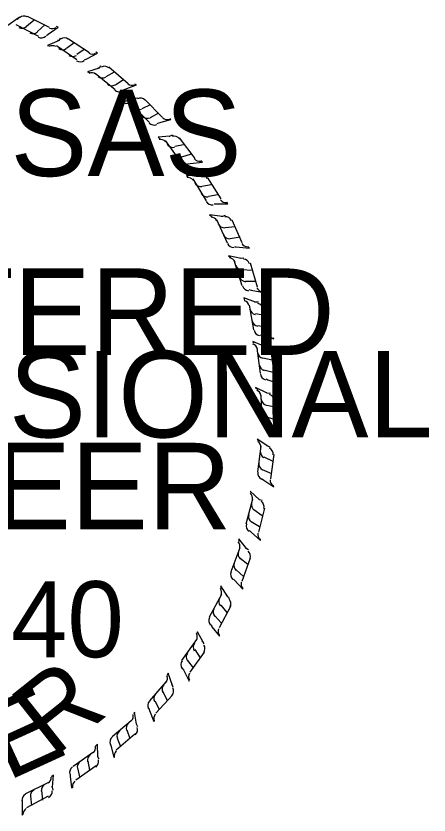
# Model space of a CAD drawing. Extents: x 1369528 to 1373075, y 373809 to 376031.
# Drawn here: x 1372751.6 to 1372841.2, y 373968.1 to 374141.3 of the extents above; entities that cross this region are included whole.
import ezdxf

# ---------------------------------------------------------------- set-up
doc = ezdxf.new("R2010")
doc.units = 0
doc.layers.add('R_Border Notes', color=7, linetype='Continuous')

msp = doc.modelspace()

# ---------------------------------------------------------------- linework, layer by layer
at = {"layer": 'R_Border Notes'}
for p, q in [((1372752.11, 374140.76), (1372749.83, 374139.2)), ((1372752.11, 374140.76), (1372751.87, 374140.52)), ((1372752.47, 374141), (1372752.11, 374140.76)), ((1372754.03, 374141.24), (1372758.83, 374138.84)), ((1372756.55, 374136.8), (1372751.63, 374139.32)), ((1372753.91, 374139.08), (1372755.59, 374140.4)), ((1372756.31, 374137.88), (1372757.87, 374139.32)), ((1372760.75, 374138.84), (1372760.39, 374138.96)), ((1372758.23, 374137.04), (1372758.59, 374137.28)), ((1372758.59, 374137.28), (1372760.75, 374138.84)), ((1372760.99, 374135.96), (1372758.47, 374134.88)), ((1372760.99, 374135.96), (1372760.63, 374135.96)), ((1372761.23, 374136.44), (1372760.99, 374135.96)), ((1372762.55, 374134.28), (1372764.23, 374135.48)), ((1372763.03, 374136.32), (1372767.59, 374133.32)), ((1372758.47, 374134.88), (1372758.83, 374134.76)), ((1372764.83, 374131.76), (1372760.39, 374134.76)), ((1372764.83, 374132.96), (1372766.39, 374134.04)), ((1372766.99, 374132), (1372769.27, 374133.2)), ((1372769.27, 374133.2), (1372768.91, 374133.44)), ((1372766.51, 374131.76), (1372766.99, 374132)), ((1372769.99, 374130.44), (1372769.63, 374129.96)), ((1372769.63, 374129.96), (1372767.11, 374129.12)), ((1372767.11, 374129.12), (1372767.59, 374129)), ((1372773.11, 374125.28), (1372768.79, 374128.76)), ((1372769.63, 374129.96), (1372769.39, 374129.96)), ((1372771.19, 374128.16), (1372772.99, 374129.12)), ((1372771.79, 374130.2), (1372775.99, 374126.6)), ((1372773.23, 374126.36), (1372775.03, 374127.56)), ((1372774.79, 374125.16), (1372775.27, 374125.4)), ((1372775.27, 374125.4), (1372777.79, 374126.36)), ((1372777.79, 374126.36), (1372777.43, 374126.48)), ((1372777.55, 374123.36), (1372775.03, 374122.64)), ((1372777.55, 374123.36), (1372777.31, 374123.12)), ((1372778.03, 374123.48), (1372777.55, 374123.36)), ((1372775.03, 374122.64), (1372775.39, 374122.28)), ((1372780.55, 374118.2), (1372776.59, 374122.16)), ((1372778.99, 374121.2), (1372780.79, 374122.04)), ((1372779.59, 374123.12), (1372783.43, 374119.28)), ((1372780.79, 374119.28), (1372782.59, 374120.24)), ((1372782.59, 374118.08), (1372785.23, 374118.8)), ((1372785.23, 374118.8), (1372784.99, 374119.04)), ((1372782.23, 374117.96), (1372782.59, 374118.08)), ((1372784.99, 374115.2), (1372782.47, 374114.96)), ((1372782.47, 374114.96), (1372782.83, 374114.6)), ((1372784.99, 374115.2), (1372784.87, 374115.08)), ((1372785.59, 374115.44), (1372784.99, 374115.2)), ((1372787.03, 374114.84), (1372790.39, 374110.4)), ((1372787.39, 374109.68), (1372784.03, 374114.24)), ((1372786.07, 374113.04), (1372787.99, 374113.4)), ((1372787.63, 374110.76), (1372789.67, 374111.36)), ((1372789.43, 374109.32), (1372792.07, 374109.56)), ((1372792.07, 374109.56), (1372791.71, 374109.92)), ((1372788.83, 374109.2), (1372789.43, 374109.32)), ((1372791.23, 374106.68), (1372788.59, 374106.68)), ((1372788.59, 374106.68), (1372788.83, 374106.32)), ((1372791.23, 374106.68), (1372790.99, 374106.8)), ((1372791.59, 374106.92), (1372791.23, 374106.68)), ((1372793.15, 374106.2), (1372796.03, 374101.64)), ((1372792.91, 374101.16), (1372790.03, 374105.96)), ((1372791.95, 374104.4), (1372793.99, 374104.76)), ((1372793.39, 374102.24), (1372795.43, 374102.6)), ((1372797.59, 374100.56), (1372797.35, 374100.92)), ((1372794.59, 374100.56), (1372794.95, 374100.56)), ((1372794.95, 374100.56), (1372797.59, 374100.56)), ((1372796.39, 374097.8), (1372793.63, 374098.16)), ((1372793.63, 374098.16), (1372794.11, 374097.8)), ((1372796.39, 374097.8), (1372796.15, 374097.8)), ((1372796.99, 374098.04), (1372796.39, 374097.8)), ((1372797.47, 374092.04), (1372795.19, 374097.08)), ((1372796.99, 374095.4), (1372799.15, 374095.64)), ((1372798.43, 374097.08), (1372800.59, 374092.16)), ((1372798.07, 374093), (1372800.23, 374093.36)), ((1372799.03, 374091.2), (1372799.39, 374091.2)), ((1372799.39, 374091.2), (1372802.27, 374090.96)), ((1372802.27, 374090.96), (1372801.91, 374091.32)), ((1372800.47, 374088.68), (1372797.71, 374089.28)), ((1372797.71, 374089.28), (1372798.19, 374088.92)), ((1372800.47, 374088.68), (1372800.23, 374088.8)), ((1372801.07, 374088.8), (1372800.47, 374088.68)), ((1372800.71, 374082.8), (1372799.03, 374088.08)), ((1372802.39, 374087.72), (1372803.95, 374082.56)), ((1372800.59, 374086.28), (1372802.87, 374086.16)), ((1372801.43, 374083.76), (1372803.59, 374083.76)), ((1372802.15, 374081.96), (1372802.63, 374081.84)), ((1372802.63, 374081.84), (1372805.39, 374081.36)), ((1372803.59, 374079.2), (1372801.07, 374080.16)), ((1372801.07, 374080.16), (1372801.19, 374079.56)), ((1372805.39, 374081.36), (1372805.03, 374081.6)), ((1372803.23, 374073.2), (1372802.27, 374078.6)), ((1372803.59, 374079.2), (1372803.35, 374079.2)), ((1372804.19, 374079.2), (1372803.59, 374079.2)), ((1372803.59, 374076.8), (1372805.63, 374076.44)), ((1372805.39, 374077.76), (1372806.35, 374072.6)), ((1372804.07, 374074.16), (1372806.11, 374073.8)), ((1372804.55, 374072.12), (1372805.03, 374072)), ((1372805.03, 374072), (1372807.55, 374071.28)), ((1372807.55, 374071.28), (1372807.43, 374071.52)), ((1372805.39, 374069.72), (1372802.99, 374070.68)), ((1372802.99, 374070.68), (1372803.11, 374070.32)), ((1372805.39, 374069.72), (1372805.15, 374069.72)), ((1372805.99, 374069.6), (1372805.39, 374069.72)), ((1372804.67, 374063.84), (1372803.95, 374069.24)), ((1372806.95, 374068.16), (1372807.67, 374062.76)), ((1372805.15, 374067.2), (1372807.19, 374066.72)), ((1372805.39, 374064.56), (1372807.43, 374064.08)), ((1372805.87, 374062.64), (1372806.23, 374062.4)), ((1372806.23, 374062.4), (1372808.75, 374061.56)), ((1372808.75, 374061.56), (1372808.63, 374061.8)), ((1372806.11, 374059.52), (1372803.59, 374060.72)), ((1372803.59, 374060.72), (1372804.07, 374060.36)), ((1372806.11, 374059.52), (1372805.99, 374059.64)), ((1372806.83, 374059.4), (1372806.11, 374059.52)), ((1372805.03, 374053.76), (1372804.79, 374059.16)), ((1372807.79, 374057.96), (1372808.15, 374052.56)), ((1372805.63, 374057), (1372807.91, 374056.52)), ((1372805.99, 374054.36), (1372808.03, 374053.76)), ((1372806.11, 374052.44), (1372806.59, 374052.2)), ((1372806.59, 374052.2), (1372808.99, 374051.12)), ((1372808.99, 374051.12), (1372808.99, 374051.36)), ((1372806.23, 374048), (1372803.95, 374049.56)), ((1372803.95, 374049.56), (1372804.19, 374049.08)), ((1372804.07, 374042.48), (1372804.79, 374048)), ((1372806.23, 374048), (1372805.99, 374048.12)), ((1372806.83, 374047.76), (1372806.23, 374048)), ((1372805.39, 374045.72), (1372807.31, 374044.76)), ((1372807.55, 374046.2), (1372806.83, 374040.92)), ((1372805.03, 374042.96), (1372807.07, 374042.12)), ((1372804.91, 374041.04), (1372805.39, 374040.68)), ((1372805.39, 374040.68), (1372807.55, 374039.24)), ((1372807.55, 374039.24), (1372807.43, 374039.6)), ((1372804.43, 374036.36), (1372802.39, 374038.28)), ((1372802.39, 374038.28), (1372802.63, 374037.8)), ((1372801.55, 374031.2), (1372802.99, 374036.6)), ((1372804.43, 374036.36), (1372804.19, 374036.6)), ((1372805.03, 374036.24), (1372804.43, 374036.36)), ((1372803.23, 374034.32), (1372805.03, 374033)), ((1372805.51, 374034.56), (1372804.19, 374029.4)), ((1372802.63, 374031.68), (1372804.43, 374030.6)), ((1372802.27, 374029.76), (1372802.63, 374029.4)), ((1372802.63, 374029.4), (1372804.67, 374027.6)), ((1372801.67, 374025.8), (1372799.99, 374027.96)), ((1372799.99, 374027.96), (1372799.99, 374027.36)), ((1372804.67, 374027.6), (1372804.67, 374027.96)), ((1372798.31, 374020.88), (1372800.23, 374026.04)), ((1372801.67, 374025.8), (1372801.43, 374025.92)), ((1372802.03, 374025.56), (1372801.67, 374025.8)), ((1372800.23, 374023.76), (1372801.91, 374022.44)), ((1372802.39, 374023.76), (1372800.59, 374018.72)), ((1372799.39, 374021.24), (1372800.95, 374019.8)), ((1372797.59, 374015.36), (1372796.03, 374017.76)), ((1372796.03, 374017.76), (1372796.03, 374017.16)), ((1372798.79, 374019.2), (1372799.03, 374018.96)), ((1372799.03, 374018.96), (1372800.83, 374017.04)), ((1372800.83, 374017.04), (1372800.83, 374017.28)), ((1372793.63, 374011.04), (1372796.27, 374015.96)), ((1372797.59, 374015.36), (1372797.47, 374015.6)), ((1372797.95, 374015), (1372797.59, 374015.36)), ((1372798.19, 374013.44), (1372795.67, 374008.64)), ((1372796.03, 374013.56), (1372797.35, 374012)), ((1372794.83, 374011.16), (1372796.15, 374009.72)), ((1372793.99, 374009.36), (1372794.11, 374008.88)), ((1372790.99, 374007.8), (1372790.87, 374007.44)), ((1372792.19, 374005.52), (1372790.99, 374007.8)), ((1372794.11, 374008.88), (1372795.79, 374006.84)), ((1372787.63, 374001.56), (1372790.87, 374006.12)), ((1372792.19, 374005.52), (1372791.95, 374005.76)), ((1372795.79, 374006.84), (1372795.79, 374007.2)), ((1372790.39, 374003.96), (1372791.59, 374002.16)), ((1372792.43, 374005.16), (1372792.19, 374005.52)), ((1372792.43, 374003.36), (1372789.31, 373999.04)), ((1372788.83, 374001.56), (1372790.03, 374000)), ((1372784.63, 373998.8), (1372784.39, 373998.32)), ((1372785.59, 373996.16), (1372784.63, 373998.8)), ((1372787.63, 374000), (1372787.99, 373999.52)), ((1372787.99, 373999.52), (1372789.19, 373997.12)), ((1372780.67, 373992.8), (1372784.27, 373997)), ((1372789.19, 373997.12), (1372789.19, 373997.48)), ((1372785.59, 373996.16), (1372785.35, 373996.4)), ((1372785.71, 373995.8), (1372785.59, 373996.16)), ((1372785.47, 373994), (1372781.99, 373990.16)), ((1372783.43, 373994.96), (1372784.39, 373992.92)), ((1372781.75, 373992.8), (1372782.71, 373991)), ((1372777.31, 373990.4), (1372777.19, 373990.04)), ((1372777.79, 373987.76), (1372777.31, 373990.4)), ((1372780.43, 373991.24), (1372780.55, 373990.76)), ((1372780.55, 373990.76), (1372781.51, 373988.36)), ((1372772.51, 373985.12), (1372776.59, 373988.6)), ((1372781.51, 373988.36), (1372781.63, 373988.6)), ((1372775.63, 373986.56), (1372776.35, 373984.64)), ((1372777.79, 373987.76), (1372777.79, 373988)), ((1372778.03, 373987.16), (1372777.79, 373987.76)), ((1372777.43, 373985.6), (1372773.35, 373982.12)), ((1372769.27, 373983.44), (1372768.79, 373982.96)), ((1372769.39, 373980.68), (1372769.27, 373983.44)), ((1372772.03, 373983.56), (1372772.27, 373982.96)), ((1372773.59, 373984.76), (1372774.31, 373982.96)), ((1372763.99, 373978.64), (1372768.43, 373981.76)), ((1372772.27, 373982.96), (1372772.87, 373980.56)), ((1372767.23, 373979.72), (1372767.59, 373977.8)), ((1372769.39, 373980.68), (1372769.39, 373981.04)), ((1372769.63, 373980.2), (1372769.39, 373980.68)), ((1372772.87, 373980.56), (1372772.99, 373980.68)), ((1372769.03, 373978.76), (1372764.59, 373975.64)), ((1372764.95, 373978.28), (1372765.43, 373976.36)), ((1372759.79, 373976.72), (1372759.31, 373976.36)), ((1372759.55, 373974.08), (1372759.79, 373976.72)), ((1372763.39, 373976.96), (1372763.39, 373976.48)), ((1372763.39, 373976.48), (1372763.63, 373973.96)), ((1372753.79, 373972.76), (1372758.59, 373975.16)), ((1372757.15, 373973.36), (1372757.39, 373971.32)), ((1372759.55, 373974.08), (1372759.43, 373974.32)), ((1372759.67, 373973.48), (1372759.55, 373974.08)), ((1372763.63, 373973.96), (1372763.99, 373974.2)), ((1372752.95, 373971.2), (1372752.95, 373970.72)), ((1372758.59, 373972.16), (1372753.91, 373969.64)), ((1372754.75, 373972.16), (1372754.99, 373970.12)), ((1372752.95, 373970.72), (1372752.95, 373968.08)), ((1372752.95, 373968.08), (1372753.19, 373968.32))]:
    msp.add_line(p, q, dxfattribs=at)
for centre, start, end in [((1372753.4, 374139.78), 63.0708, 131.4448), ((1372752.93, 374140.11), 243.0708, 311.4448), ((1372755.28, 374138.9), 243.0708, 311.4448), ((1372759.47, 374139.98), 247.3316, 306.1194), ((1372757.11, 374137.98), 243.0708, 311.4448), ((1372762.13, 374135.03), 56.1736, 124.5476), ((1372759.54, 374133.33), 60.4344, 119.2222), ((1372761.7, 374135.41), 236.1736, 304.5476), ((1372763.89, 374133.93), 236.1736, 304.5476), ((1372768.18, 374134.49), 240.4344, 299.2222), ((1372765.6, 374132.8), 236.1736, 304.5476), ((1372770.79, 374128.88), 50.1902, 118.5642), ((1372768.04, 374127.46), 54.451, 113.2388), ((1372770.4, 374129.31), 230.1902, 298.5642), ((1372772.43, 374127.61), 230.1902, 298.5642), ((1372774.01, 374126.3), 230.1902, 298.5642), ((1372776.75, 374127.72), 234.451, 293.2388), ((1372778.59, 374121.97), 44.9655, 113.3394), ((1372775.73, 374120.8), 49.2262, 108.0141), ((1372778.25, 374122.43), 224.9655, 293.3394), ((1372780.11, 374120.55), 224.9655, 293.3394), ((1372784.43, 374120.27), 229.2262, 288.0141), ((1372781.57, 374119.1), 224.9655, 293.3394), ((1372785.9, 374113.75), 36.6897, 105.0637), ((1372782.9, 374113.01), 40.9505, 99.7383), ((1372785.63, 374114.26), 216.6897, 285.0637), ((1372787.2, 374112.13), 216.6897, 285.0637), ((1372788.43, 374110.49), 216.6897, 285.0637), ((1372791.43, 374111.23), 220.9505, 279.7383), ((1372788.85, 374104.79), 36.0034, 94.7913), ((1372791.9, 374105.26), 31.7427, 100.1166), ((1372791.68, 374105.79), 211.7427, 280.1166), ((1372793.06, 374103.54), 211.7427, 280.1166), ((1372794.14, 374101.8), 211.7427, 280.1166), ((1372797.2, 374102.28), 216.0034, 274.7913), ((1372793.91, 374096.17), 29.1451, 87.9329), ((1372797, 374096.28), 24.8843, 93.2583), ((1372796.84, 374096.83), 204.8843, 273.2583), ((1372797.94, 374094.43), 204.8843, 273.2583), ((1372798.81, 374092.57), 204.8843, 273.2583), ((1372801.9, 374092.68), 209.1451, 267.9329), ((1372797.76, 374087.37), 22.0938, 80.8817), ((1372800.75, 374087.67), 197.8331, 266.207), ((1372800.84, 374087.1), 17.8331, 86.207), ((1372801.55, 374085.15), 197.8331, 266.207), ((1372802.18, 374083.2), 197.8331, 266.207), ((1372805.26, 374082.93), 202.0938, 260.8817), ((1372800.77, 374078.08), 15.7912, 74.579), ((1372803.81, 374077.48), 11.5304, 79.9044), ((1372803.78, 374078.05), 191.5304, 259.9044), ((1372804.29, 374075.46), 191.5304, 259.9044), ((1372804.71, 374073.45), 191.5304, 259.9044), ((1372807.74, 374072.84), 195.7912, 254.579), ((1372802.52, 374068.77), 11.4348, 70.2226), ((1372805.51, 374068.52), 187.174, 255.548), ((1372805.5, 374067.94), 7.174, 75.548), ((1372805.83, 374065.89), 187.174, 255.548), ((1372806.09, 374063.86), 187.174, 255.548), ((1372809.07, 374063.02), 191.4348, 250.2226), ((1372803.26, 374058.8), 8.033, 66.8208), ((1372806.23, 374058.37), 183.7722, 252.1462), ((1372806.18, 374057.79), 3.7722, 72.1462), ((1372806.4, 374055.73), 183.7722, 252.1462), ((1372806.54, 374053.68), 183.7722, 252.1462), ((1372809.46, 374052.67), 188.033, 246.8208), ((1372803.25, 374047.81), 357.57, 56.3579), ((1372805.94, 374046.29), 353.3093, 61.6832), ((1372806.09, 374046.85), 173.3093, 241.6832), ((1372805.77, 374044.22), 173.3093, 241.6832), ((1372805.54, 374042.18), 173.3093, 241.6832), ((1372808.23, 374040.66), 177.57, 236.3579), ((1372801.47, 374036.67), 350.445, 49.2329), ((1372804.17, 374035.36), 166.1842, 234.5582), ((1372803.95, 374034.83), 346.1842, 54.5582), ((1372803.53, 374032.79), 166.1842, 234.5582), ((1372803.04, 374030.8), 166.1842, 234.5582), ((1372805.52, 374028.95), 170.445, 229.2329), ((1372798.73, 374026.27), 344.1611, 42.9489), ((1372801.27, 374024.67), 159.9003, 228.2743), ((1372800.99, 374024.16), 339.9003, 48.2743), ((1372800.35, 374022.19), 159.9003, 228.2743), ((1372799.65, 374020.26), 159.9003, 228.2743), ((1372801.91, 374018.15), 164.1611, 222.9489), ((1372794.75, 374016.3), 337.1149, 35.9028), ((1372797.08, 374014.4), 152.8541, 221.2281), ((1372796.74, 374013.93), 332.8541, 41.2281), ((1372795.86, 374012.05), 152.8541, 221.2281), ((1372794.93, 374010.22), 152.8541, 221.2281), ((1372789.47, 374006.7), 329.7262, 28.514), ((1372796.92, 374007.85), 157.1149, 215.9028), ((1372791.53, 374004.52), 145.4654, 213.8394), ((1372791.13, 374004.1), 325.4654, 33.8394), ((1372790.02, 374002.35), 145.4654, 213.8394), ((1372788.86, 374000.66), 145.4654, 213.8394), ((1372790.53, 373998.05), 149.7262, 208.514), ((1372782.99, 373997.73), 322.7822, 21.57), ((1372784.77, 373995.31), 138.5214, 206.8953), ((1372784.33, 373994.94), 318.5214, 26.8953), ((1372783.01, 373993.34), 138.5214, 206.8953), ((1372781.66, 373991.79), 138.5214, 206.8953), ((1372775.59, 373989.54), 314.7826, 13.5704), ((1372783, 373989.01), 142.7822, 201.57), ((1372777.02, 373986.9), 130.5218, 198.8958), ((1372776.53, 373986.6), 310.5218, 18.8958), ((1372773.45, 373983.85), 130.5218, 198.8958), ((1372775.01, 373985.19), 130.5218, 198.8958), ((1372767.43, 373982.72), 308.9134, 7.7012), ((1372774.39, 373980.91), 134.7826, 193.5704), ((1372766.4, 373978.46), 124.6526, 193.0266), ((1372768.59, 373979.95), 124.6526, 193.0266), ((1372768.07, 373979.7), 304.6526, 13.0266), ((1372764.72, 373977.28), 124.6526, 193.0266), ((1372757.81, 373976.3), 301.0994, 359.8872), ((1372758.57, 373973.4), 116.8386, 185.2126), ((1372765.35, 373974.26), 128.9134, 187.7013), ((1372756.21, 373972.21), 116.8386, 185.2126), ((1372758.02, 373973.22), 296.8386, 5.2126), ((1372754.38, 373971.28), 116.8386, 185.2126), ((1372754.59, 373968.2), 121.0994, 179.8872)]:
    msp.add_arc(centre, 1.48, start, end, dxfattribs=at)

# ---------------------------------------------------------------- texts
for s, height, p in [('ARKANSAS', 18.749, (1372664.03, 374106.56)), ('REGISTERED', 18.749, (1372657.79, 374067.8)), ('PROFESSIONAL', 18.7488, (1372646.99, 374049.92)), ('ENGINEER', 18.749, (1372667.39, 374030)), ('No. 8940', 16.471, (1372685.63, 374002.28))]:
    msp.add_text(s, height=height, dxfattribs=at).set_placement(p)
for s, rotation, p in [('R', 38.3946, (1372759.55, 373980.2)), ('E', 24.5342, (1372749.83, 373975.4))]:
    msp.add_text(s, height=16.41, rotation=rotation, dxfattribs=at).set_placement(p)

doc.saveas('drawing.dxf')
